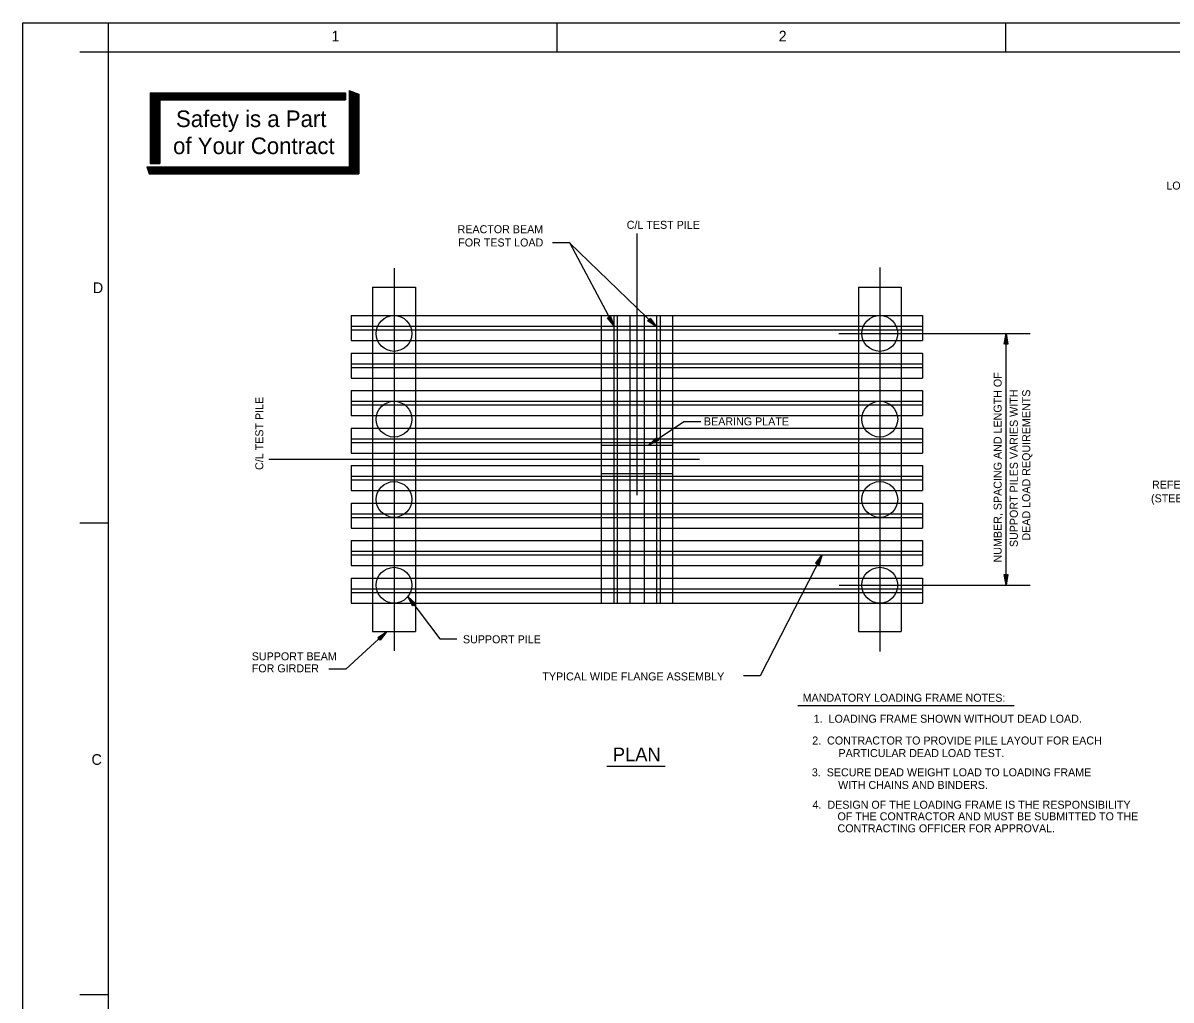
# Model space of a CAD drawing. Extents: x 22378.6 to 22422.6, y 22377.7 to 22411.7.
# Drawn here: x 22378.63 to 22398.72, y 22394.56 to 22411.66 of the extents above; entities that cross this region are included whole.
import ezdxf

# ---------------------------------------------------------------- set-up
doc = ezdxf.new("R2010")
doc.units = 0
for name, color, linetype in [('Level 1', 7, 'Continuous'), ('Level 10', 7, 'Continuous'), ('Level 2', 7, 'Continuous'), ('Level 3', 7, 'Continuous'), ('Level 4', 7, 'Continuous'), ('Level 7', 7, 'Continuous'), ('Level 9', 7, 'Continuous')]:
    doc.layers.add(name, color=color, linetype=linetype)

msp = doc.modelspace()

# ---------------------------------------------------------------- linework, layer by layer
at = {"layer": 'Level 1'}
for p, q in [((22389.372, 22407.974), (22389.372, 22403.394)), ((22385.122, 22407.367), (22385.122, 22400.673)), ((22393.622, 22407.381), (22393.622, 22400.659)), ((22388.948, 22406.396), (22388.948, 22406.396)), ((22388.973, 22406.35), (22388.973, 22406.35)), ((22389.678, 22406.376), (22389.678, 22406.376)), ((22389.716, 22406.339), (22389.716, 22406.339)), ((22392.906, 22406.225), (22396.254, 22406.225)), ((22395.832, 22406.225), (22395.832, 22406.225)), ((22395.832, 22401.819), (22395.832, 22406.225)), ((22395.832, 22406.173), (22395.832, 22406.173)), ((22389.575, 22404.272), (22389.575, 22404.272)), ((22389.618, 22404.3), (22389.618, 22404.3)), ((22382.933, 22404.022), (22390.465, 22404.022)), ((22392.587, 22402.303), (22392.587, 22402.303)), ((22392.611, 22402.35), (22392.611, 22402.35)), ((22395.832, 22401.871), (22395.832, 22401.871)), ((22392.912, 22401.819), (22396.251, 22401.819)), ((22395.832, 22401.819), (22395.832, 22401.819)), ((22385.363, 22401.62), (22385.363, 22401.62)), ((22385.395, 22401.579), (22385.395, 22401.579)), ((22384.96, 22400.971), (22384.96, 22400.971)), ((22384.999, 22401.006), (22384.999, 22401.006))]:
    msp.add_line(p, q, dxfattribs=at)
msp.add_lwpolyline([(22378.629, 22411.659), (22422.645, 22411.659), (22422.645, 22377.651), (22378.629, 22377.651)], close=True, dxfattribs=at)
for points in [[(22389.716, 22406.339), (22388.191, 22407.813), (22387.895, 22407.813)], [(22388.973, 22406.35), (22388.197, 22407.812), (22387.901, 22407.812)], [(22388.912, 22406.53), (22388.973, 22406.35), (22388.858, 22406.5), (22388.904, 22406.525), (22388.948, 22406.396), (22388.87, 22406.498), (22388.9, 22406.514), (22388.925, 22406.44), (22388.883, 22406.496), (22388.895, 22406.502), (22388.9, 22406.486)], [(22389.603, 22406.492), (22389.716, 22406.339), (22389.56, 22406.447), (22389.596, 22406.485), (22389.678, 22406.376), (22389.572, 22406.449), (22389.596, 22406.473), (22389.642, 22406.41), (22389.585, 22406.45), (22389.595, 22406.46), (22389.605, 22406.446)], [(22395.801, 22406.038), (22395.832, 22406.225), (22395.863, 22406.038), (22395.81, 22406.038), (22395.832, 22406.173), (22395.853, 22406.046), (22395.819, 22406.046), (22395.832, 22406.123), (22395.843, 22406.054), (22395.829, 22406.054), (22395.832, 22406.071)], [(22389.575, 22404.272), (22390.196, 22404.684), (22390.492, 22404.684)], [(22389.748, 22404.349), (22389.575, 22404.272), (22389.714, 22404.401), (22389.743, 22404.357), (22389.618, 22404.3), (22389.712, 22404.388), (22389.731, 22404.36), (22389.66, 22404.328), (22389.711, 22404.375), (22389.719, 22404.364), (22389.703, 22404.357)], [(22392.611, 22402.35), (22391.531, 22400.23), (22391.235, 22400.23)], [(22392.498, 22402.197), (22392.611, 22402.35), (22392.554, 22402.169), (22392.506, 22402.193), (22392.587, 22402.303), (22392.548, 22402.181), (22392.518, 22402.196), (22392.565, 22402.259), (22392.543, 22402.192), (22392.531, 22402.199), (22392.541, 22402.213)], [(22395.863, 22402.006), (22395.832, 22401.819), (22395.801, 22402.006), (22395.854, 22402.006), (22395.832, 22401.871), (22395.811, 22401.998), (22395.845, 22401.998), (22395.832, 22401.921), (22395.821, 22401.99), (22395.835, 22401.99), (22395.832, 22401.973)], [(22385.363, 22401.62), (22385.925, 22400.88), (22386.221, 22400.88)], [(22385.452, 22401.453), (22385.363, 22401.62), (22385.501, 22401.49), (22385.459, 22401.458), (22385.395, 22401.579), (22385.488, 22401.49), (22385.461, 22401.47), (22385.425, 22401.539), (22385.475, 22401.491), (22385.464, 22401.482), (22385.456, 22401.498)], [(22384.999, 22401.006), (22384.278, 22400.352), (22383.982, 22400.352)], [(22384.839, 22400.903), (22384.999, 22401.006), (22384.881, 22400.857), (22384.845, 22400.897), (22384.96, 22400.971), (22384.88, 22400.87), (22384.857, 22400.895), (22384.923, 22400.937), (22384.879, 22400.883), (22384.87, 22400.893), (22384.885, 22400.903)]]:
    msp.add_lwpolyline(points, dxfattribs=at)
at = {"layer": 'Level 10'}
for p, q in [((22380.129, 22411.155), (22380.129, 22411.659)), ((22387.977, 22411.155), (22387.977, 22411.659)), ((22395.825, 22411.155), (22395.825, 22411.659)), ((22379.625, 22411.155), (22380.129, 22411.155)), ((22384.337, 22410.475), (22384.337, 22409.141)), ((22384.337, 22410.475), (22384.504, 22410.413)), ((22384.348, 22410.471), (22384.348, 22409.016)), ((22380.857, 22410.438), (22384.274, 22410.438)), ((22380.857, 22410.438), (22380.857, 22409.197)), ((22380.857, 22410.422), (22384.274, 22410.422)), ((22380.857, 22410.407), (22384.274, 22410.407)), ((22380.857, 22410.391), (22384.274, 22410.391)), ((22380.857, 22410.375), (22384.274, 22410.375)), ((22380.857, 22410.36), (22384.274, 22410.36)), ((22380.857, 22410.344), (22384.274, 22410.344)), ((22380.857, 22410.329), (22384.274, 22410.329)), ((22380.873, 22410.438), (22380.873, 22409.197)), ((22380.888, 22410.438), (22380.888, 22409.197)), ((22380.904, 22410.438), (22380.904, 22409.197)), ((22380.919, 22410.438), (22380.919, 22409.197)), ((22380.935, 22410.438), (22380.935, 22409.197)), ((22380.951, 22410.438), (22380.951, 22409.197)), ((22380.966, 22410.438), (22380.966, 22409.197)), ((22380.982, 22410.438), (22380.982, 22409.197)), ((22380.998, 22410.438), (22380.998, 22409.197)), ((22381.013, 22410.438), (22381.013, 22409.197)), ((22381.024, 22410.313), (22384.274, 22410.313)), ((22381.024, 22410.313), (22381.024, 22409.197)), ((22384.274, 22410.438), (22384.274, 22410.313)), ((22384.363, 22410.465), (22384.363, 22409.016)), ((22384.379, 22410.459), (22384.379, 22409.016)), ((22384.395, 22410.453), (22384.395, 22409.016)), ((22384.41, 22410.448), (22384.41, 22409.016)), ((22384.426, 22410.442), (22384.426, 22409.016)), ((22384.441, 22410.436), (22384.441, 22409.016)), ((22384.457, 22410.43), (22384.457, 22409.016)), ((22384.473, 22410.425), (22384.473, 22409.016)), ((22384.488, 22410.413), (22384.488, 22409.016)), ((22384.504, 22410.413), (22384.504, 22409.016)), ((22380.794, 22409.141), (22384.337, 22409.141)), ((22380.794, 22409.141), (22380.84, 22409.016)), ((22380.8, 22409.125), (22384.348, 22409.125)), ((22380.805, 22409.11), (22384.348, 22409.11)), ((22380.811, 22409.094), (22384.348, 22409.094)), ((22380.817, 22409.078), (22384.348, 22409.078)), ((22380.823, 22409.063), (22384.348, 22409.063)), ((22380.857, 22409.197), (22381.024, 22409.197)), ((22380.829, 22409.047), (22384.348, 22409.047)), ((22380.834, 22409.032), (22384.348, 22409.032)), ((22380.84, 22409.016), (22384.504, 22409.016)), ((22379.625, 22402.911), (22380.129, 22402.911)), ((22388.843, 22398.649), (22389.864, 22398.649)), ((22379.625, 22394.655), (22380.129, 22394.655))]:
    msp.add_line(p, q, dxfattribs=at)
at = {"layer": 'Level 2'}
for p, q in [((22384.747, 22406.537), (22384.747, 22406.1)), ((22385.497, 22406.537), (22385.497, 22406.1)), ((22388.747, 22406.537), (22388.747, 22406.1)), ((22388.966, 22406.537), (22388.966, 22401.506)), ((22389.028, 22406.537), (22389.028, 22401.506)), ((22389.247, 22406.537), (22389.247, 22406.1)), ((22389.497, 22406.537), (22389.497, 22406.1)), ((22389.716, 22406.537), (22389.716, 22401.506)), ((22389.778, 22406.537), (22389.778, 22401.506)), ((22389.997, 22406.537), (22389.997, 22406.1)), ((22393.247, 22406.537), (22393.247, 22406.1)), ((22393.997, 22406.537), (22393.997, 22406.1)), ((22384.372, 22406.35), (22394.372, 22406.35)), ((22384.372, 22406.287), (22394.372, 22406.287)), ((22384.747, 22405.881), (22384.747, 22405.444)), ((22385.497, 22405.881), (22385.497, 22405.444)), ((22388.747, 22405.881), (22388.747, 22405.444)), ((22389.247, 22405.881), (22389.247, 22405.444)), ((22389.497, 22405.881), (22389.497, 22405.444)), ((22389.997, 22405.881), (22389.997, 22405.444)), ((22393.247, 22405.881), (22393.247, 22405.444)), ((22393.997, 22405.881), (22393.997, 22405.444)), ((22384.372, 22405.694), (22394.372, 22405.694)), ((22384.372, 22405.631), (22394.372, 22405.631)), ((22384.747, 22405.225), (22384.747, 22404.787)), ((22385.497, 22405.225), (22385.497, 22404.787)), ((22388.747, 22405.225), (22388.747, 22404.787)), ((22389.247, 22405.225), (22389.247, 22404.787)), ((22389.497, 22405.225), (22389.497, 22404.787)), ((22389.997, 22405.225), (22389.997, 22404.787)), ((22393.247, 22405.225), (22393.247, 22404.787)), ((22393.997, 22405.225), (22393.997, 22404.787)), ((22384.372, 22405.037), (22394.372, 22405.037)), ((22384.372, 22404.975), (22394.372, 22404.975)), ((22384.747, 22404.569), (22384.747, 22404.131)), ((22385.497, 22404.569), (22385.497, 22404.131)), ((22388.747, 22404.569), (22388.747, 22404.131)), ((22389.247, 22404.569), (22389.247, 22404.131)), ((22389.497, 22404.569), (22389.497, 22404.131)), ((22389.997, 22404.569), (22389.997, 22404.131)), ((22393.247, 22404.569), (22393.247, 22404.131)), ((22393.997, 22404.569), (22393.997, 22404.131)), ((22384.372, 22404.381), (22394.372, 22404.381)), ((22384.372, 22404.319), (22394.372, 22404.319)), ((22388.747, 22404.272), (22389.997, 22404.272)), ((22384.747, 22403.912), (22384.747, 22403.475)), ((22385.497, 22403.912), (22385.497, 22403.475)), ((22388.747, 22403.912), (22388.747, 22403.475)), ((22389.247, 22403.912), (22389.247, 22403.475)), ((22389.497, 22403.912), (22389.497, 22403.475)), ((22389.997, 22403.912), (22389.997, 22403.475)), ((22393.247, 22403.912), (22393.247, 22403.475)), ((22393.997, 22403.912), (22393.997, 22403.475)), ((22384.372, 22403.725), (22394.372, 22403.725)), ((22384.372, 22403.662), (22394.372, 22403.662)), ((22388.747, 22403.772), (22389.997, 22403.772)), ((22384.747, 22403.256), (22384.747, 22402.819)), ((22385.497, 22403.256), (22385.497, 22402.819)), ((22388.747, 22403.256), (22388.747, 22402.819)), ((22389.247, 22403.256), (22389.247, 22402.819)), ((22389.497, 22403.256), (22389.497, 22402.819)), ((22389.997, 22403.256), (22389.997, 22402.819)), ((22393.247, 22403.256), (22393.247, 22402.819)), ((22393.997, 22403.256), (22393.997, 22402.819)), ((22384.372, 22403.069), (22394.372, 22403.069)), ((22384.372, 22403.006), (22394.372, 22403.006)), ((22384.747, 22402.6), (22384.747, 22402.162)), ((22385.497, 22402.6), (22385.497, 22402.162)), ((22388.747, 22402.6), (22388.747, 22402.162)), ((22389.247, 22402.6), (22389.247, 22402.162)), ((22389.497, 22402.6), (22389.497, 22402.162)), ((22389.997, 22402.6), (22389.997, 22402.162)), ((22393.247, 22402.6), (22393.247, 22402.162)), ((22393.997, 22402.6), (22393.997, 22402.162)), ((22384.372, 22402.412), (22394.372, 22402.412)), ((22384.372, 22402.35), (22394.372, 22402.35)), ((22384.747, 22401.944), (22384.747, 22401.506)), ((22385.497, 22401.944), (22385.497, 22401.506)), ((22388.747, 22401.944), (22388.747, 22401.506)), ((22389.247, 22401.944), (22389.247, 22401.506)), ((22389.497, 22401.944), (22389.497, 22401.506)), ((22389.997, 22401.944), (22389.997, 22401.506)), ((22393.247, 22401.944), (22393.247, 22401.506)), ((22393.997, 22401.944), (22393.997, 22401.506)), ((22384.372, 22401.756), (22394.372, 22401.756)), ((22384.372, 22401.694), (22394.372, 22401.694))]:
    msp.add_line(p, q, dxfattribs=at)
for centre in [(22385.122, 22406.225), (22393.622, 22406.225), (22385.122, 22404.725), (22393.622, 22404.725), (22385.122, 22403.319), (22393.622, 22403.319), (22385.122, 22401.819), (22393.622, 22401.819)]:
    msp.add_circle(centre, 0.313, dxfattribs=at)
at = {"layer": 'Level 7'}
for p, q in [((22384.747, 22407.037), (22384.747, 22406.537)), ((22384.747, 22407.037), (22385.497, 22407.037)), ((22385.497, 22407.037), (22385.497, 22406.537)), ((22393.247, 22407.037), (22393.247, 22406.537)), ((22393.247, 22407.037), (22393.997, 22407.037)), ((22393.997, 22407.037), (22393.997, 22406.537)), ((22384.372, 22406.537), (22394.372, 22406.537)), ((22384.372, 22406.537), (22384.372, 22406.1)), ((22394.372, 22406.537), (22394.372, 22406.1)), ((22384.372, 22406.1), (22394.372, 22406.1)), ((22384.747, 22406.1), (22384.747, 22405.881)), ((22385.497, 22406.1), (22385.497, 22405.881)), ((22388.747, 22406.1), (22388.747, 22405.881)), ((22389.247, 22406.1), (22389.247, 22405.881)), ((22389.497, 22406.1), (22389.497, 22405.881)), ((22389.997, 22406.1), (22389.997, 22405.881)), ((22393.247, 22406.1), (22393.247, 22405.881)), ((22393.997, 22406.1), (22393.997, 22405.881)), ((22384.372, 22405.881), (22394.372, 22405.881)), ((22384.372, 22405.881), (22384.372, 22405.444)), ((22394.372, 22405.881), (22394.372, 22405.444)), ((22384.372, 22405.444), (22394.372, 22405.444)), ((22384.747, 22405.444), (22384.747, 22405.225)), ((22385.497, 22405.444), (22385.497, 22405.225)), ((22388.747, 22405.444), (22388.747, 22405.225)), ((22389.247, 22405.444), (22389.247, 22405.225)), ((22389.497, 22405.444), (22389.497, 22405.225)), ((22389.997, 22405.444), (22389.997, 22405.225)), ((22393.247, 22405.444), (22393.247, 22405.225)), ((22393.997, 22405.444), (22393.997, 22405.225)), ((22384.372, 22405.225), (22394.372, 22405.225)), ((22384.372, 22405.225), (22384.372, 22404.787)), ((22394.372, 22405.225), (22394.372, 22404.787)), ((22384.372, 22404.787), (22394.372, 22404.787)), ((22384.747, 22404.787), (22384.747, 22404.569)), ((22385.497, 22404.787), (22385.497, 22404.569)), ((22388.747, 22404.787), (22388.747, 22404.569)), ((22389.247, 22404.787), (22389.247, 22404.569)), ((22389.497, 22404.787), (22389.497, 22404.569)), ((22389.997, 22404.787), (22389.997, 22404.569)), ((22393.247, 22404.787), (22393.247, 22404.569)), ((22393.997, 22404.787), (22393.997, 22404.569)), ((22384.372, 22404.569), (22394.372, 22404.569)), ((22384.372, 22404.569), (22384.372, 22404.131)), ((22394.372, 22404.569), (22394.372, 22404.131)), ((22384.372, 22404.131), (22394.372, 22404.131)), ((22384.747, 22404.131), (22384.747, 22403.912)), ((22385.497, 22404.131), (22385.497, 22403.912)), ((22388.747, 22404.131), (22388.747, 22403.912)), ((22389.247, 22404.131), (22389.247, 22403.912)), ((22389.497, 22404.131), (22389.497, 22403.912)), ((22389.997, 22404.131), (22389.997, 22403.912)), ((22393.247, 22404.131), (22393.247, 22403.912)), ((22393.997, 22404.131), (22393.997, 22403.912)), ((22384.372, 22403.912), (22394.372, 22403.912)), ((22384.372, 22403.912), (22384.372, 22403.475)), ((22394.372, 22403.912), (22394.372, 22403.475)), ((22384.372, 22403.475), (22394.372, 22403.475)), ((22384.747, 22403.475), (22384.747, 22403.256)), ((22385.497, 22403.475), (22385.497, 22403.256)), ((22388.747, 22403.475), (22388.747, 22403.256)), ((22389.247, 22403.475), (22389.247, 22403.256)), ((22389.497, 22403.475), (22389.497, 22403.256)), ((22389.997, 22403.475), (22389.997, 22403.256)), ((22393.247, 22403.475), (22393.247, 22403.256)), ((22393.997, 22403.475), (22393.997, 22403.256)), ((22384.372, 22403.256), (22394.372, 22403.256)), ((22384.372, 22403.256), (22384.372, 22402.819)), ((22394.372, 22403.256), (22394.372, 22402.819)), ((22384.372, 22402.819), (22394.372, 22402.819)), ((22384.747, 22402.819), (22384.747, 22402.6)), ((22385.497, 22402.819), (22385.497, 22402.6)), ((22388.747, 22402.819), (22388.747, 22402.6)), ((22389.247, 22402.819), (22389.247, 22402.6)), ((22389.497, 22402.819), (22389.497, 22402.6)), ((22389.997, 22402.819), (22389.997, 22402.6)), ((22393.247, 22402.819), (22393.247, 22402.6)), ((22393.997, 22402.819), (22393.997, 22402.6)), ((22384.372, 22402.6), (22394.372, 22402.6)), ((22384.372, 22402.6), (22384.372, 22402.162)), ((22394.372, 22402.6), (22394.372, 22402.162)), ((22384.372, 22402.162), (22394.372, 22402.162)), ((22384.747, 22402.162), (22384.747, 22401.944)), ((22385.497, 22402.162), (22385.497, 22401.944)), ((22388.747, 22402.162), (22388.747, 22401.944)), ((22389.247, 22402.162), (22389.247, 22401.944)), ((22389.497, 22402.162), (22389.497, 22401.944)), ((22389.997, 22402.162), (22389.997, 22401.944)), ((22393.247, 22402.162), (22393.247, 22401.944)), ((22393.997, 22402.162), (22393.997, 22401.944)), ((22384.372, 22401.944), (22394.372, 22401.944)), ((22384.372, 22401.944), (22384.372, 22401.506)), ((22394.372, 22401.944), (22394.372, 22401.506)), ((22384.372, 22401.506), (22394.372, 22401.506)), ((22384.747, 22401.506), (22384.747, 22401.006)), ((22385.497, 22401.506), (22385.497, 22401.006)), ((22393.247, 22401.506), (22393.247, 22401.006)), ((22393.997, 22401.506), (22393.997, 22401.006)), ((22384.747, 22401.006), (22385.497, 22401.006)), ((22393.247, 22401.006), (22393.997, 22401.006)), ((22392.188, 22399.714), (22395.975, 22399.714))]:
    msp.add_line(p, q, dxfattribs=at)
at = {"layer": 'Level 9'}
for p, q in [((22380.129, 22378.155), (22380.129, 22411.155)), ((22380.129, 22411.155), (22419.393, 22411.155))]:
    msp.add_line(p, q, dxfattribs=at)

# ---------------------------------------------------------------- texts
at = {"layer": 'Level 1'}
for s, p in [('1', (22384.029, 22411.335)), ('2', (22391.853, 22411.335)), ('D', (22379.853, 22406.931)), ('C', (22379.829, 22398.675))]:
    msp.add_text(s, height=0.187, dxfattribs=at).set_placement(p)
at = {"layer": 'Level 10'}
for s, p in [('Safety is a Part', (22381.307, 22409.837)), ('of Your Contract', (22381.256, 22409.364))]:
    msp.add_text(s, height=0.29038, dxfattribs=at).set_placement(p)
at = {"layer": 'Level 3'}
msp.add_text('PLAN', height=0.24, dxfattribs=at).set_placement((22388.95, 22398.737))
at = {"layer": 'Level 4'}
for s, p in [('LOADING FRAME MEMBERS', (22398.636, 22408.743)), ('REACTOR BEAM', (22386.234, 22407.979)), ('C/L TEST PILE', (22389.194, 22408.056)), ('FOR TEST LOAD', (22386.246, 22407.747)), ('BEARING PLATE', (22390.545, 22404.616)), ('REFERENCE BEAM', (22398.385, 22403.509)), ('(STEEL OR WOOD)', (22398.368, 22403.269)), ('SUPPORT PILE', (22386.328, 22400.802)), ('SUPPORT BEAM', (22382.633, 22400.504)), ('FOR GIRDER', (22382.633, 22400.294)), ('TYPICAL WIDE FLANGE ASSEMBLY', (22387.717, 22400.152)), ('MANDATORY LOADING FRAME NOTES:', (22392.272, 22399.779)), ('1.  LOADING FRAME SHOWN WITHOUT DEAD LOAD.', (22392.466, 22399.412)), ('2.  CONTRACTOR TO PROVIDE PILE LAYOUT FOR EACH', (22392.44, 22399.031)), ('PARTICULAR DEAD LOAD TEST.', (22392.899, 22398.811)), ('3.  SECURE DEAD WEIGHT LOAD TO LOADING FRAME', (22392.433, 22398.474)), ('WITH CHAINS AND BINDERS.', (22392.893, 22398.253)), ('4.  DESIGN OF THE LOADING FRAME IS THE RESPONSIBILITY ', (22392.445, 22397.907)), ('OF THE CONTRACTOR AND MUST BE SUBMITTED TO THE', (22392.882, 22397.704)), ('CONTRACTING OFFICER FOR APPROVAL.', (22392.882, 22397.494))]:
    msp.add_text(s, height=0.14, dxfattribs=at).set_placement(p)
for s, p in [('NUMBER, SPACING AND LENGTH OF', (22395.754, 22402.217)), ('C/L TEST PILE', (22382.835, 22403.836)), ('SUPPORT PILES VARIES WITH', (22396.037, 22402.486)), ('DEAD LOAD REQUIREMENTS', (22396.254, 22402.6))]:
    msp.add_text(s, height=0.14, rotation=90, dxfattribs=at).set_placement(p)

doc.saveas('drawing.dxf')
